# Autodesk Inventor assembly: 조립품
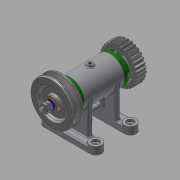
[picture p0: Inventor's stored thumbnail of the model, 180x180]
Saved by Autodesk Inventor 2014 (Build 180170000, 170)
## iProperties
Created: 2015-11
Part Number: 조립품
Document SubType Name: Assembly
Designer: Owner
Author: Owner
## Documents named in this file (13)
- C:\Documents and Settings\Owner\바탕 화면\451109V1007\조립품.iam
- C:\Documents and Settings\Owner\바탕 화면\451109V1007\본체.ipt
- C:\Documents and Settings\Owner\바탕 화면\451109V1007\베어링 15 x 32 x 9.ipt
- C:\Documents and Settings\Owner\바탕 화면\451109V1007\커버.ipt
- C:\Documents and Settings\Owner\바탕 화면\451109V1007\오일 실 15 25 7.ipt
- C:\Documents and Settings\Owner\바탕 화면\451109V1007\볼트 M4 x 12.ipt
- C:\Documents and Settings\Owner\바탕 화면\451109V1007\축.ipt
- C:\Documents and Settings\Owner\바탕 화면\451109V1007\키 3 x 3 x 12.ipt
- C:\Documents and Settings\Owner\바탕 화면\451109V1007\V벨트풀리.ipt
- C:\Documents and Settings\Owner\바탕 화면\451109V1007\스퍼기어.ipt
- C:\Documents and Settings\Owner\바탕 화면\451109V1007\와셔 8x17.ipt
- C:\Documents and Settings\Owner\바탕 화면\451109V1007\스프링와셔 8.ipt
- C:\Documents and Settings\Owner\바탕 화면\451109V1007\너트 M 8.ipt
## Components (11 placed, 3 different names)
1. KS B 2023 6002 - 15 x 32 x 9:1
2. KS B 2023 6002 - 15 x 32 x 9:2
3. V벨트풀리:1
4. ISO 4762 M4 x 12:1
5. ISO 4762 M4 x 12:2
6. ISO 4762 M4 x 12:3
7. ISO 4762 M4 x 12:4
8. ISO 4762 M4 x 12:5
9. ISO 4762 M4 x 12:6
10. ISO 4762 M4 x 12:7
11. ISO 4762 M4 x 12:8
